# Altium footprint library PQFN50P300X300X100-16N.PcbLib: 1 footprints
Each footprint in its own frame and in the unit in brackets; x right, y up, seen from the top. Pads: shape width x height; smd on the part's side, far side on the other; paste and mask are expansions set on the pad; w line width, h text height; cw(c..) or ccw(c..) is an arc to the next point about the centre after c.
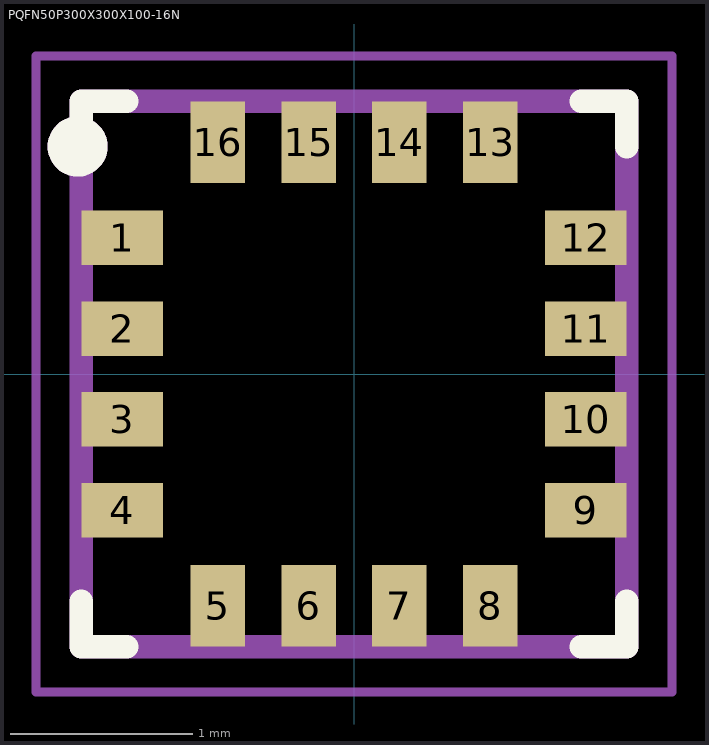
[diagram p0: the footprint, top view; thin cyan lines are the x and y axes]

## PQFN50P300X300X100-16N [mm]
pads (16):
  rect 0.45x0.3 smd: 1(-1.275,0.75) 2(-1.275,0.25) 3(-1.275,-0.25) 4(-1.275,-0.75) 9(1.275,-0.75) 10(1.275,-0.25) 11(1.275,0.25) 12(1.275,0.75)
  rect 0.3x0.45 smd: 5(-0.75,-1.275) 6(-0.25,-1.275) 7(0.25,-1.275) 8(0.75,-1.275) 13(0.75,1.275) 14(0.25,1.275) 15(-0.25,1.275) 16(-0.75,1.275)
Top Overlay:
  circle w0.178: c-1.52,1.251 r0.076
  lines w0.127: -1.5,-1.25 -1.5,-1.5 -1.25,-1.5 ; -1.5,1.25 -1.5,1.5 -1.25,1.5 ; 1.25,-1.5 1.5,-1.5 1.5,-1.25 ; 1.25,1.5 1.5,1.5 1.5,1.25
Mechanical 13:
  circle w0.178: c-1.52,1.251 r0.076
  lines w0.127: -1.5,-1.5 1.5,-1.5 1.5,1.5 -1.5,1.5 -1.5,-1.5
Mechanical 15:
  lines w0.05: -1.75,-1.75 1.75,-1.75 1.75,1.75 -1.75,1.75 -1.75,-1.75
3D body "step_temp.STEP": height 1, standoff 0, extent -1.5,-1.5 1.5,1.5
